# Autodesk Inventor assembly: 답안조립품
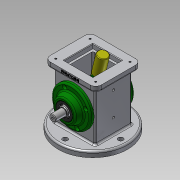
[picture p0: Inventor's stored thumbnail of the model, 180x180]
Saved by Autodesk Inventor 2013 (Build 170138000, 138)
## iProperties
Created: 2018-10
Part Number: 답안조립품
Document SubType Name: Assembly
Designer: hana-max10
Author: hana-max10
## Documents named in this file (11)
- C:\Documents and Settings\hana-max10\바탕 화면\481007V1038\답안조립품.iam
- C:\Documents and Settings\hana-max10\바탕 화면\481007V1038\본체.ipt
- C:\Documents and Settings\hana-max10\바탕 화면\481007V1038\편심축.ipt
- C:\Documents and Settings\hana-max10\바탕 화면\481007V1038\링크.ipt
- C:\Documents and Settings\hana-max10\바탕 화면\481007V1038\클레비스 핀 6 x 22.ipt
- 클레비스 핀 6 x 22.ipt
- C:\Documents and Settings\hana-max10\바탕 화면\481007V1038\슬라이더.ipt
- C:\Documents and Settings\hana-max10\바탕 화면\481007V1038\베어링 17 x 40 x 12.ipt
- C:\Documents and Settings\hana-max10\바탕 화면\481007V1038\뒤커버.ipt
- C:\Documents and Settings\hana-max10\바탕 화면\481007V1038\앞커버.ipt
- C:\Documents and Settings\hana-max10\바탕 화면\481007V1038\오일 실 17 30 8.ipt
